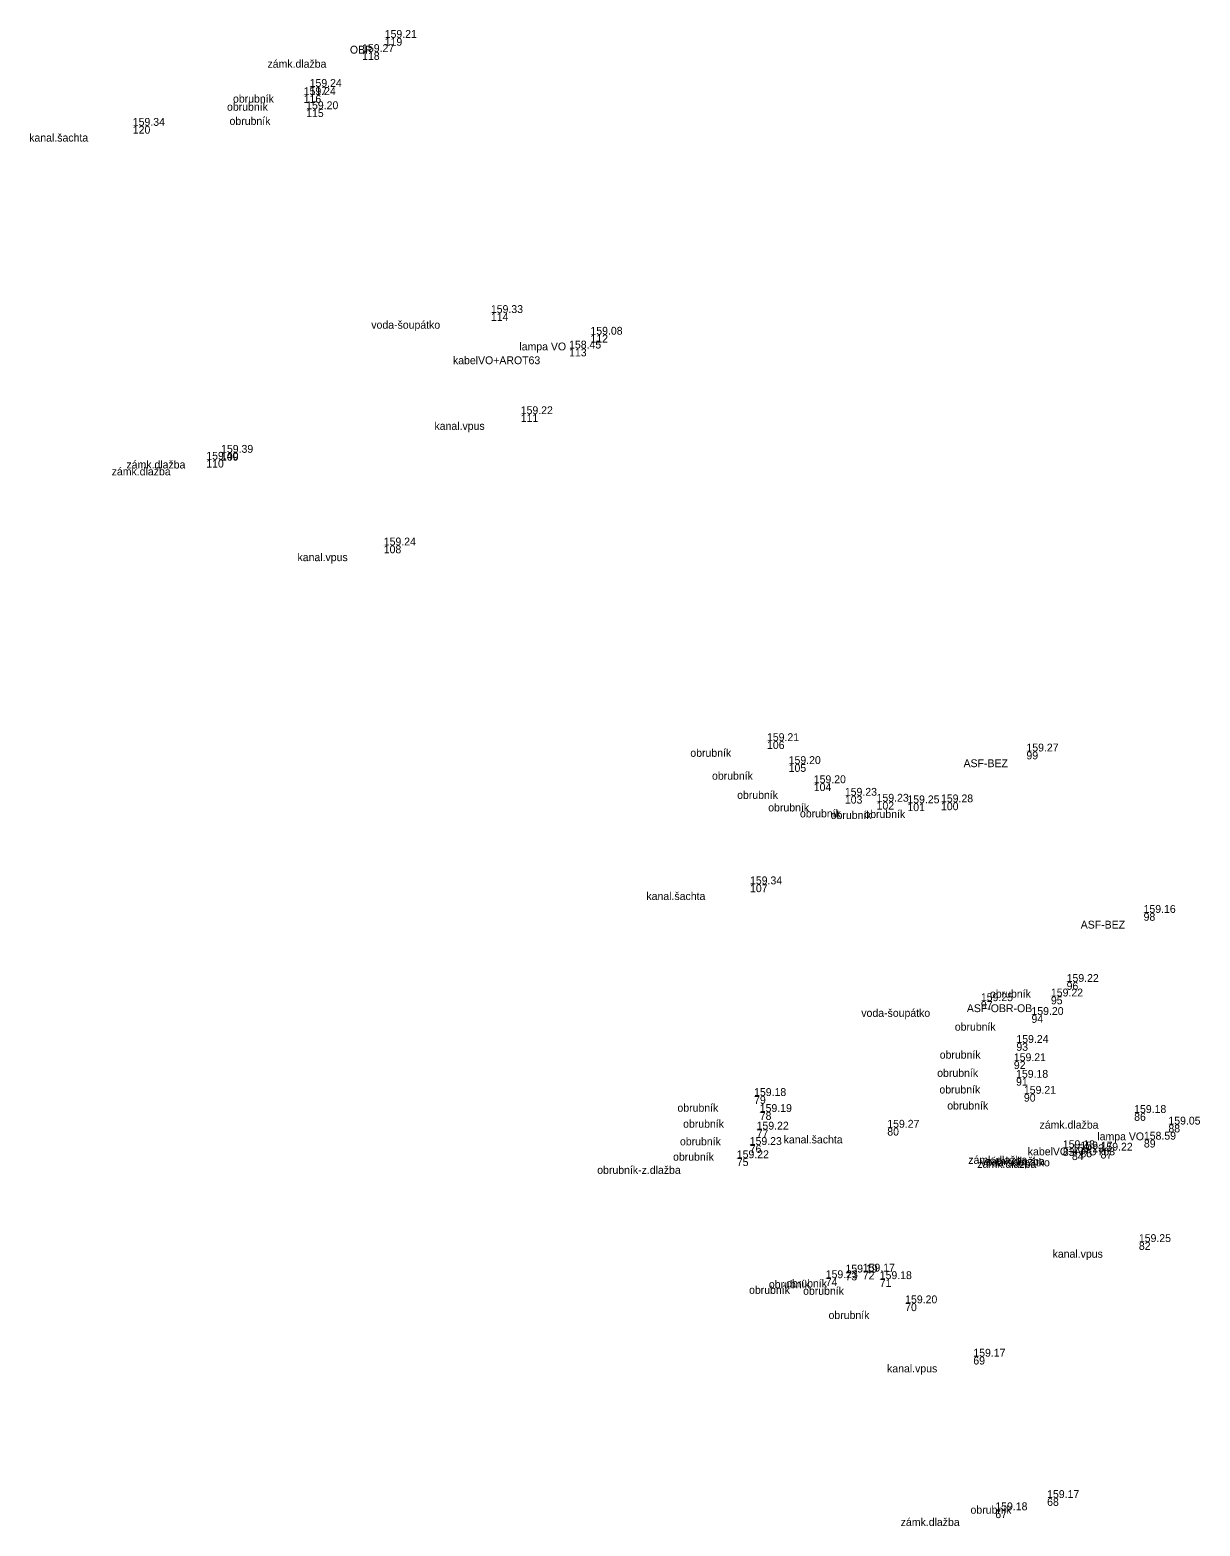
# Model space of a CAD drawing. Extents: x -583304 to -583163, y -1211038 to -1210841.
# Drawn here: x -583228.98 to -583191.72, y -1210990.72 to -1210943.09 of the extents above; entities that cross this region are included whole.
import ezdxf

# ---------------------------------------------------------------- set-up
doc = ezdxf.new("R2010")
doc.units = 0
for name, color, linetype in [('Vrstva 10', 7, 'Continuous'), ('Vrstva 7', 7, 'Continuous'), ('Vrstva 8', 7, 'Continuous'), ('Vrstva 9', 7, 'Continuous')]:
    doc.layers.add(name, color=color, linetype=linetype)

msp = doc.modelspace()

# ---------------------------------------------------------------- linework, layer by layer
at = {"layer": 'Vrstva 7'}
for p, q in [((-583218.4, -1210943.79), (-583218.4, -1210943.79)), ((-583217.68, -1210943.34), (-583217.68, -1210943.34)), ((-583220.26, -1210945.16), (-583220.26, -1210945.16)), ((-583220.07, -1210944.9), (-583220.07, -1210944.9)), ((-583220.18, -1210945.61), (-583220.18, -1210945.61)), ((-583225.7, -1210946.14), (-583225.7, -1210946.14)), ((-583214.3, -1210952.1), (-583214.3, -1210952.1)), ((-583211.13, -1210952.79), (-583211.13, -1210952.79)), ((-583211.81, -1210953.23), (-583211.81, -1210953.23)), ((-583213.35, -1210955.32), (-583213.35, -1210955.32)), ((-583222.89, -1210956.55), (-583222.89, -1210956.55)), ((-583223.36, -1210956.77), (-583223.36, -1210956.77)), ((-583217.71, -1210959.5), (-583217.71, -1210959.5)), ((-583205.51, -1210965.73), (-583205.51, -1210965.73)), ((-583197.25, -1210966.06), (-583197.25, -1210966.06)), ((-583204.82, -1210966.46), (-583204.82, -1210966.46)), ((-583204.02, -1210967.07), (-583204.02, -1210967.07)), ((-583203.03, -1210967.47), (-583203.03, -1210967.47)), ((-583202.02, -1210967.66), (-583202.02, -1210967.66)), ((-583201.04, -1210967.71), (-583201.04, -1210967.71)), ((-583199.97, -1210967.68), (-583199.97, -1210967.68)), ((-583206.05, -1210970.29), (-583206.05, -1210970.29)), ((-583193.52, -1210971.2), (-583193.52, -1210971.2)), ((-583195.97, -1210973.4), (-583195.97, -1210973.4)), ((-583198.7, -1210974.01), (-583198.7, -1210974.01)), ((-583196.47, -1210973.86), (-583196.47, -1210973.86)), ((-583197.09, -1210974.45), (-583197.09, -1210974.45)), ((-583197.57, -1210975.34), (-583197.57, -1210975.34)), ((-583197.65, -1210975.92), (-583197.65, -1210975.92)), ((-583197.58, -1210976.45), (-583197.58, -1210976.45)), ((-583205.92, -1210977.03), (-583205.92, -1210977.03)), ((-583197.33, -1210976.96), (-583197.33, -1210976.96)), ((-583205.74, -1210977.54), (-583205.74, -1210977.54)), ((-583193.82, -1210977.57), (-583193.82, -1210977.57)), ((-583205.84, -1210978.1), (-583205.84, -1210978.1)), ((-583201.68, -1210978.04), (-583201.68, -1210978.04)), ((-583192.73, -1210977.94), (-583192.73, -1210977.94)), ((-583193.51, -1210978.42), (-583193.51, -1210978.42)), ((-583206.47, -1210979.01), (-583206.47, -1210979.01)), ((-583206.06, -1210978.59), (-583206.06, -1210978.59)), ((-583196.09, -1210978.69), (-583196.09, -1210978.69)), ((-583195.8, -1210978.82), (-583195.8, -1210978.82)), ((-583195.53, -1210978.73), (-583195.53, -1210978.73)), ((-583194.89, -1210978.77), (-583194.89, -1210978.77)), ((-583193.67, -1210981.68), (-583193.67, -1210981.68)), ((-583203.64, -1210982.83), (-583203.64, -1210982.83)), ((-583203.01, -1210982.65), (-583203.01, -1210982.65)), ((-583202.46, -1210982.62), (-583202.46, -1210982.62)), ((-583201.92, -1210982.86), (-583201.92, -1210982.86)), ((-583201.11, -1210983.63), (-583201.11, -1210983.63)), ((-583198.94, -1210985.33), (-583198.94, -1210985.33)), ((-583196.59, -1210989.83), (-583196.59, -1210989.83)), ((-583198.24, -1210990.22), (-583198.24, -1210990.22))]:
    msp.add_line(p, q, dxfattribs=at)

# ---------------------------------------------------------------- texts
at = {"layer": 'Vrstva 10'}
for s, p in [('OBR', (-583218.788, -1210943.84)), ('zámk.dlažba', (-583221.412, -1210944.29)), ('obrubník', (-583222.51, -1210945.4)), ('obrubník', (-583222.7, -1210945.66)), ('obrubník', (-583222.62, -1210946.11)), ('kanal.šachta', (-583228.998, -1210946.64)), ('voda-šoupátko', (-583218.107, -1210952.6)), ('lampa VO', (-583213.392, -1210953.29)), ('kabelVO+AROT63', (-583215.507, -1210953.73)), ('kanal.vpus', (-583216.096, -1210955.82)), ('zámk.dlažba', (-583226.372, -1210957.27)), ('zámk.dlažba', (-583225.902, -1210957.05)), ('kanal.vpus', (-583220.456, -1210960)), ('obrubník', (-583207.95, -1210966.23)), ('ASF-BEZ', (-583199.251, -1210966.56)), ('obrubník', (-583207.26, -1210966.96)), ('obrubník', (-583206.46, -1210967.57)), ('obrubník', (-583205.47, -1210967.97)), ('obrubník', (-583204.46, -1210968.16)), ('obrubník', (-583203.48, -1210968.21)), ('obrubník', (-583202.41, -1210968.18)), ('kanal.šachta', (-583209.348, -1210970.79)), ('ASF-BEZ', (-583195.521, -1210971.7)), ('obrubník', (-583198.41, -1210973.9)), ('voda-šoupátko', (-583202.507, -1210974.51)), ('ASF-OBR-OB', (-583199.146, -1210974.36)), ('obrubník', (-583199.53, -1210974.95)), ('obrubník', (-583200.01, -1210975.84)), ('obrubník', (-583200.09, -1210976.42)), ('obrubník', (-583200.02, -1210976.95)), ('obrubník', (-583208.36, -1210977.53)), ('obrubník', (-583199.77, -1210977.46)), ('obrubník', (-583208.18, -1210978.04)), ('zámk.dlažba', (-583196.832, -1210978.07)), ('obrubník', (-583208.28, -1210978.6)), ('kanal.šachta', (-583204.978, -1210978.54)), ('lampa VO', (-583194.992, -1210978.44)), ('obrubník', (-583208.5, -1210979.09)), ('zámk.dlažba', (-583199.102, -1210979.19)), ('zámk.dlažba', (-583198.812, -1210979.32)), ('voda-šoupátko', (-583198.697, -1210979.27)), ('zámk.dlažba', (-583198.542, -1210979.23)), ('kabelVO+AROT63', (-583197.207, -1210978.92)), ('obrubník-z.dlažba', (-583210.914, -1210979.51)), ('kanal.vpus', (-583196.416, -1210982.18)), ('obrubník', (-583204.9, -1210983.12)), ('obrubník', (-583206.08, -1210983.33)), ('obrubník', (-583205.45, -1210983.15)), ('obrubník', (-583204.36, -1210983.36)), ('obrubník', (-583203.55, -1210984.13)), ('kanal.vpus', (-583201.686, -1210985.83)), ('zámk.dlažba', (-583201.252, -1210990.72)), ('obrubník', (-583199.03, -1210990.33))]:
    msp.add_text(s, height=0.25, dxfattribs=at).set_placement(p)
at = {"layer": 'Vrstva 8'}
for s, p in [('118', (-583218.4, -1210944.04)), ('119', (-583217.68, -1210943.59)), ('116', (-583220.26, -1210945.41)), ('117', (-583220.07, -1210945.15)), ('115', (-583220.18, -1210945.86)), ('120', (-583225.7, -1210946.39)), ('114', (-583214.3, -1210952.35)), ('112', (-583211.13, -1210953.04)), ('113', (-583211.81, -1210953.48)), ('111', (-583213.35, -1210955.57)), ('109', (-583222.89, -1210956.8)), ('110', (-583223.36, -1210957.02)), ('108', (-583217.71, -1210959.75)), ('106', (-583205.51, -1210965.98)), ('99', (-583197.25, -1210966.31)), ('105', (-583204.82, -1210966.71)), ('104', (-583204.02, -1210967.32)), ('103', (-583203.03, -1210967.72)), ('102', (-583202.02, -1210967.91)), ('101', (-583201.04, -1210967.96)), ('100', (-583199.97, -1210967.93)), ('107', (-583206.05, -1210970.54)), ('98', (-583193.52, -1210971.45)), ('96', (-583195.97, -1210973.65)), ('97', (-583198.7, -1210974.26)), ('95', (-583196.47, -1210974.11)), ('94', (-583197.09, -1210974.7)), ('93', (-583197.57, -1210975.59)), ('92', (-583197.65, -1210976.17)), ('91', (-583197.58, -1210976.7)), ('79', (-583205.92, -1210977.28)), ('90', (-583197.33, -1210977.21)), ('78', (-583205.74, -1210977.79)), ('86', (-583193.82, -1210977.82)), ('77', (-583205.84, -1210978.35)), ('80', (-583201.68, -1210978.29)), ('88', (-583192.73, -1210978.19)), ('89', (-583193.51, -1210978.67)), ('75', (-583206.47, -1210979.26)), ('76', (-583206.06, -1210978.84)), ('83', (-583196.09, -1210978.94)), ('84', (-583195.8, -1210979.07)), ('85', (-583195.53, -1210978.98)), ('87', (-583194.89, -1210979.02)), ('82', (-583193.67, -1210981.93)), ('74', (-583203.64, -1210983.08)), ('73', (-583203.01, -1210982.9)), ('72', (-583202.46, -1210982.87)), ('71', (-583201.92, -1210983.11)), ('70', (-583201.11, -1210983.88)), ('69', (-583198.94, -1210985.58)), ('68', (-583196.59, -1210990.08)), ('67', (-583198.24, -1210990.47))]:
    msp.add_text(s, height=0.25, dxfattribs=at).set_placement(p)
at = {"layer": 'Vrstva 9'}
for s, p in [('159.21 ', (-583217.68, -1210943.34)), ('159.27 ', (-583218.4, -1210943.79)), ('159.24 ', (-583220.07, -1210944.9)), ('159.24 ', (-583220.26, -1210945.16)), ('159.20 ', (-583220.18, -1210945.61)), ('159.34 ', (-583225.7, -1210946.14)), ('159.33 ', (-583214.3, -1210952.1)), ('159.08 ', (-583211.13, -1210952.79)), ('158.45 ', (-583211.81, -1210953.23)), ('159.22 ', (-583213.35, -1210955.32)), ('159.40 ', (-583223.36, -1210956.77)), ('159.39 ', (-583222.89, -1210956.55)), ('159.24 ', (-583217.71, -1210959.5)), ('159.21 ', (-583205.51, -1210965.73)), ('159.27 ', (-583197.25, -1210966.06)), ('159.20 ', (-583204.82, -1210966.46)), ('159.20 ', (-583204.02, -1210967.07)), ('159.23 ', (-583203.03, -1210967.47)), ('159.23 ', (-583202.02, -1210967.66)), ('159.25 ', (-583201.04, -1210967.71)), ('159.28 ', (-583199.97, -1210967.68)), ('159.34 ', (-583206.05, -1210970.29)), ('159.16 ', (-583193.52, -1210971.2)), ('159.22 ', (-583195.97, -1210973.4)), ('159.25 ', (-583198.7, -1210974.01)), ('159.22 ', (-583196.47, -1210973.86)), ('159.20 ', (-583197.09, -1210974.45)), ('159.24 ', (-583197.57, -1210975.34)), ('159.21 ', (-583197.65, -1210975.92)), ('159.18 ', (-583197.58, -1210976.45)), ('159.18 ', (-583205.92, -1210977.03)), ('159.21 ', (-583197.33, -1210976.96)), ('159.19 ', (-583205.74, -1210977.54)), ('159.18 ', (-583193.82, -1210977.57)), ('159.22 ', (-583205.84, -1210978.1)), ('159.27 ', (-583201.68, -1210978.04)), ('159.05 ', (-583192.73, -1210977.94)), ('159.23 ', (-583206.06, -1210978.59)), ('159.18 ', (-583196.09, -1210978.69)), ('159.23 ', (-583195.8, -1210978.82)), ('159.17 ', (-583195.53, -1210978.73)), ('159.22 ', (-583194.89, -1210978.77)), ('158.59 ', (-583193.51, -1210978.42)), ('159.22 ', (-583206.47, -1210979.01)), ('159.25 ', (-583193.67, -1210981.68)), ('159.17 ', (-583202.46, -1210982.62)), ('159.23 ', (-583203.64, -1210982.83)), ('159.19 ', (-583203.01, -1210982.65)), ('159.18 ', (-583201.92, -1210982.86)), ('159.20 ', (-583201.11, -1210983.63)), ('159.17 ', (-583198.94, -1210985.33)), ('159.18 ', (-583198.24, -1210990.22)), ('159.17 ', (-583196.59, -1210989.83))]:
    msp.add_text(s, height=0.25, dxfattribs=at).set_placement(p)

doc.saveas('drawing.dxf')
